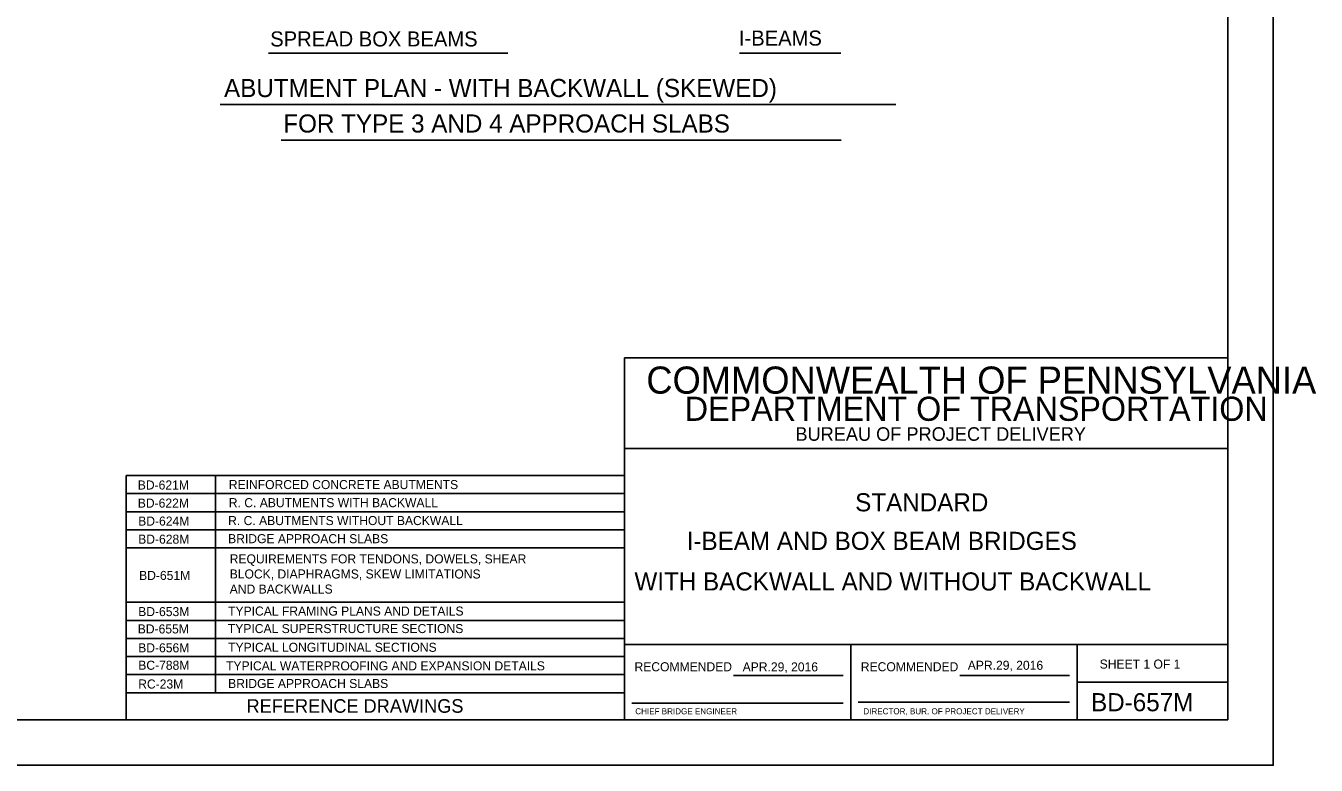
# Model space of a CAD drawing. Extents: x 640058 to 640913, y 299411 to 300005.
# Drawn here: x 640485.4 to 640913, y 299411.4 to 299656.5 of the extents above; entities that cross this region are included whole.
import ezdxf

# ---------------------------------------------------------------- set-up
doc = ezdxf.new("R2010")
doc.units = 0
doc.layers.add('1', color=7, linetype='Continuous')
doc.layers.add('PLT-BNDY', color=7, linetype='Continuous')

msp = doc.modelspace()

# ---------------------------------------------------------------- linework, layer by layer
at = {"layer": '1'}
for p, q in [((640883.79, 299990.45), (640883.79, 299426.45)), ((640565.88, 299647.43), (640645.1, 299647.43)), ((640721.89, 299647.43), (640755.45, 299647.43)), ((640549.81, 299630.37), (640773.69, 299630.37)), ((640570.07, 299618.62), (640755.57, 299618.62)), ((640883.79, 299546.45), (640683.79, 299546.45)), ((640683.79, 299546.45), (640683.79, 299426.45)), ((640883.79, 299426.45), (640883.79, 299546.45)), ((640883.79, 299516.45), (640683.79, 299516.45)), ((640518.62, 299426.45), (640518.62, 299507.45)), ((640683.79, 299507.45), (640518.62, 299507.45)), ((640548.31, 299507.45), (640548.31, 299435.45)), ((640683.79, 299501.45), (640518.62, 299501.45)), ((640683.79, 299495.45), (640518.62, 299495.45)), ((640683.79, 299489.45), (640518.62, 299489.45)), ((640518.62, 299483.45), (640683.79, 299483.45)), ((640518.62, 299465.45), (640683.79, 299465.45)), ((640518.62, 299459.45), (640683.79, 299459.45)), ((640518.62, 299453.45), (640683.79, 299453.45)), ((640883.79, 299451.45), (640683.79, 299451.45)), ((640758.79, 299426.45), (640758.79, 299451.45)), ((640833.79, 299451.45), (640833.79, 299426.45)), ((640518.62, 299447.45), (640683.79, 299447.45)), ((640683.79, 299441.45), (640518.62, 299441.45)), ((640719.88, 299441.16), (640756.29, 299441.16)), ((640794.88, 299441.16), (640831.29, 299441.16)), ((640518.62, 299435.45), (640683.79, 299435.45)), ((640833.79, 299438.95), (640883.79, 299438.95)), ((640686.29, 299431.95), (640756.29, 299431.95)), ((640761.29, 299432.32), (640831.29, 299432.32)), ((640883.79, 299426.45), (640097.69, 299426.45)), ((640898.79, 299411.45), (640898.79, 299411.45))]:
    msp.add_line(p, q, dxfattribs=at)
at = {"layer": 'PLT-BNDY'}
msp.add_lwpolyline([(640057.79, 299411.45), (640898.79, 299411.45), (640898.79, 300005.45), (640057.79, 300005.45)], close=True, dxfattribs=at)

# ---------------------------------------------------------------- texts
at = {"layer": '1'}
for s, height, p in [('SPREAD BOX BEAMS', 5, (640566.4, 299649.64)), ('I-BEAMS', 5, (640721.72, 299649.93)), ('ABUTMENT PLAN - WITH BACKWALL (SKEWED)', 6, (640551.1, 299632.87)), ('FOR TYPE 3 AND 4 APPROACH SLABS', 6, (640570.73, 299621.12)), ('COMMONWEALTH OF PENNSYLVANIA', 9, (640691.04, 299534.57)), ('DEPARTMENT OF TRANSPORTATION', 8.0002, (640703.79, 299525.57)), ('BUREAU OF PROJECT DELIVERY', 4.5, (640740.45, 299518.95)), ('BD-621M', 3, (640522.52, 299502.81)), ('REINFORCED CONCRETE ABUTMENTS', 3, (640552.68, 299502.95)), ('BD-622M', 3, (640522.52, 299496.81)), ('R. C. ABUTMENTS WITH BACKWALL', 3, (640552.68, 299496.95)), ('STANDARD', 6, (640760.25, 299495.57)), ('BD-624M', 3, (640522.65, 299490.85)), ('R. C. ABUTMENTS WITHOUT BACKWALL', 3, (640552.45, 299491.02)), ('BD-628M', 3, (640522.65, 299484.85)), ('BRIDGE APPROACH SLABS', 3, (640552.45, 299485.02)), ('I-BEAM AND BOX BEAM BRIDGES', 6, (640704.42, 299482.79)), ('REQUIREMENTS FOR TENDONS, DOWELS, SHEAR', 3, (640552.98, 299478.32)), ('BD-651M', 3, (640522.95, 299472.84)), ('BLOCK, DIAPHRAGMS, SKEW LIMITATIONS ', 3, (640552.98, 299473.32)), ('WITH BACKWALL AND WITHOUT BACKWALL', 6, (640687.1, 299469.35)), ('AND BACKWALLS', 3, (640552.98, 299468.32)), ('BD-653M', 3, (640522.65, 299460.85)), ('TYPICAL FRAMING PLANS AND DETAILS', 3, (640552.45, 299461.02)), ('BD-655M', 3, (640522.51, 299455.11)), ('TYPICAL SUPERSTRUCTURE SECTIONS', 3, (640552.37, 299455.23)), ('TYPICAL LONGITUDINAL SECTIONS', 3, (640552.45, 299449.02)), ('BD-656M', 3, (640522.65, 299448.85)), ('BC-788M', 3, (640522.67, 299443.07)), ('TYPICAL WATERPROOFING AND EXPANSION DETAILS', 3, (640551.77, 299442.87)), ('RECOMMENDED', 3, (640687.12, 299442.57)), ('APR.29, 2016', 3, (640722.96, 299442.53)), ('RECOMMENDED', 3, (640762.12, 299442.57)), ('APR.29, 2016', 3, (640797.56, 299443.06)), ('SHEET 1 OF 1', 3, (640841.28, 299443.46)), ('RC-23M', 3, (640522.65, 299436.85)), ('BRIDGE APPROACH SLABS', 3, (640552.45, 299437.02)), ('BD-657M', 6, (640838.42, 299429.32)), ('REFERENCE DRAWINGS', 4.5, (640558.56, 299428.82)), ('CHIEF BRIDGE ENGINEER', 2.0002, (640687.38, 299428.32)), ('DIRECTOR, BUR. OF PROJECT DELIVERY', 2.0002, (640762.95, 299428.32))]:
    msp.add_text(s, height=height, dxfattribs=at).set_placement(p)

doc.saveas('drawing.dxf')
